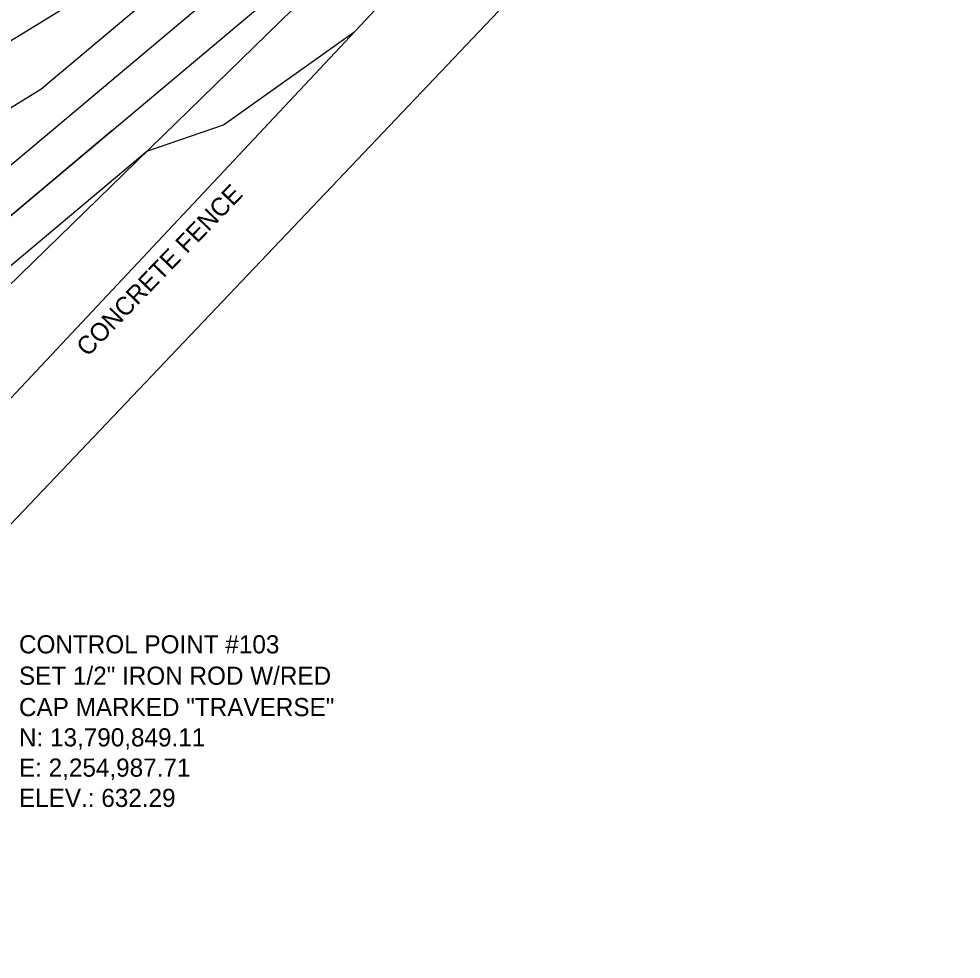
# Model space of a CAD drawing. Extents: x 2250985 to 2256614, y 13788357 to 13792478.
# Drawn here: x 2255021.5 to 2255083.8, y 13790807 to 13790869.2 of the extents above; entities that cross this region are included whole.
import ezdxf

# ---------------------------------------------------------------- set-up
doc = ezdxf.new("R2010")
doc.units = 0
for name, color, linetype in [('E_Control_Control Point See GPS AZM_CP_ANNO', 7, 'Continuous'), ('E_DTM_Contours_Minor Contours', 7, 'Continuous'), ('E_DTM_Grade Break_GB', 7, 'Continuous'), ('E_Structure_Fence_Wire Fence_WFN', 7, 'Continuous'), ('E_Structure_Fence_Wire Fence_WFN_ANNO', 7, 'Continuous'), ('E_Utility_Water_Water Line_WL', 7, 'Continuous'), ('Major Contours', 7, 'Continuous'), ('Minor Contours', 7, 'Continuous')]:
    doc.layers.add(name, color=color, linetype=linetype)

msp = doc.modelspace()

# ---------------------------------------------------------------- linework, layer by layer
at = {"layer": 'E_DTM_Contours_Minor Contours'}
for points in [[(2255000.453, 13790850.729), (2255022.941, 13790864.54), (2255046.917, 13790884.682), (2255053.28, 13790890.023), (2255064.192, 13790896.068), (2255073.64, 13790901.554)], [(2255008.101, 13790842.091), (2255029.945, 13790860.441), (2255035.016, 13790862.195), (2255039.76, 13790865.565)], [(2255013.048, 13790849.574), (2255027.674, 13790861.862)]]:
    msp.add_lwpolyline(points, dxfattribs=at)
at = {"layer": 'E_DTM_Grade Break_GB'}
msp.add_lwpolyline([(2255140.52, 13790870.17), (2255116.19, 13790882.87), (2255088.06, 13790898.9), (2255078.95, 13790902.61), (2255074.73, 13790901.33), (2255060.36, 13790889.38), (2255050.78, 13790880.74), (2255002.66, 13790833.86), (2254985.81, 13790818.82), (2254983.76, 13790810.16)], dxfattribs=at)
at = {"layer": 'E_Structure_Fence_Wire Fence_WFN'}
msp.add_lwpolyline([(2255060.11, 13790885.88), (2255007.24, 13790829.52), (2254997.6, 13790819.51)], dxfattribs=at)
at = {"layer": 'E_Utility_Water_Water Line_WL'}
msp.add_line((2254983.99, 13790796.95), (2255155.42, 13790977.17), dxfattribs=at)
at = {"layer": 'Major Contours'}
msp.add_lwpolyline([(2255011.716, 13790862.092), (2255027.887, 13790872.023), (2255045.128, 13790886.508), (2255049.704, 13790890.348), (2255066.128, 13790899.446), (2255074.427, 13790904.264), (2255078.226, 13790903.937), (2255079.329, 13790904.095), (2255080.555, 13790904.266), (2255088.23, 13790902.223)], dxfattribs=at)
at = {"layer": 'Minor Contours'}
for points in [[(2255000.453, 13790850.729), (2255022.941, 13790864.54), (2255046.917, 13790884.682), (2255053.28, 13790890.023), (2255064.192, 13790896.068), (2255074.646, 13790902.138), (2255076.786, 13790901.954), (2255078.513, 13790901.939), (2255078.775, 13790901.854)], [(2254990.756, 13790839.88), (2254991.376, 13790840.413), (2254992.531, 13790841.419), (2255017.994, 13790857.057), (2255048.705, 13790882.857), (2255056.856, 13790889.698), (2255062.257, 13790892.69), (2255069.162, 13790896.699), (2255070.846, 13790897.187), (2255074.148, 13790897.857)], [(2254991.406, 13790835.156), (2254995.799, 13790838.981), (2255013.048, 13790849.574), (2255050.494, 13790881.032), (2255059.296, 13790888.42), (2255060.346, 13790889.18), (2255060.416, 13790889.299), (2255064.582, 13790890.504), (2255065.622, 13790890.715)], [(2254970.547, 13790820.387), (2254970.527, 13790820.357), (2254977.477, 13790817.525), (2254982.332, 13790822.278), (2254983.074, 13790822.666), (2254987.864, 13790826.79), (2254999.066, 13790836.542), (2255008.101, 13790842.091), (2255029.945, 13790860.441), (2255035.016, 13790862.195), (2255043.634, 13790868.317)]]:
    msp.add_lwpolyline(points, dxfattribs=at)

# ---------------------------------------------------------------- texts
at = {"layer": 'E_Control_Control Point See GPS AZM_CP_ANNO'}
for s, p in [('CONTROL POINT #103', (2255021.5, 13790827.255)), ('SET 1/2" IRON ROD W/RED ', (2255021.5, 13790825.181)), ('CAP MARKED "TRAVERSE"', (2255021.5, 13790823.107)), ('N: 13,790,849.11', (2255021.5, 13790821.107)), ('E: 2,254,987.71', (2255021.5, 13790819.107)), ('ELEV.: 632.29', (2255021.5, 13790817.107))]:
    msp.add_text(s, height=1.2, dxfattribs=at).set_placement(p)
at = {"layer": 'E_Structure_Fence_Wire Fence_WFN_ANNO'}
msp.add_text('CONCRETE FENCE', height=1.2, rotation=46.07872, dxfattribs=at).set_placement((2255026.04, 13790846.808))

doc.saveas('drawing.dxf')
